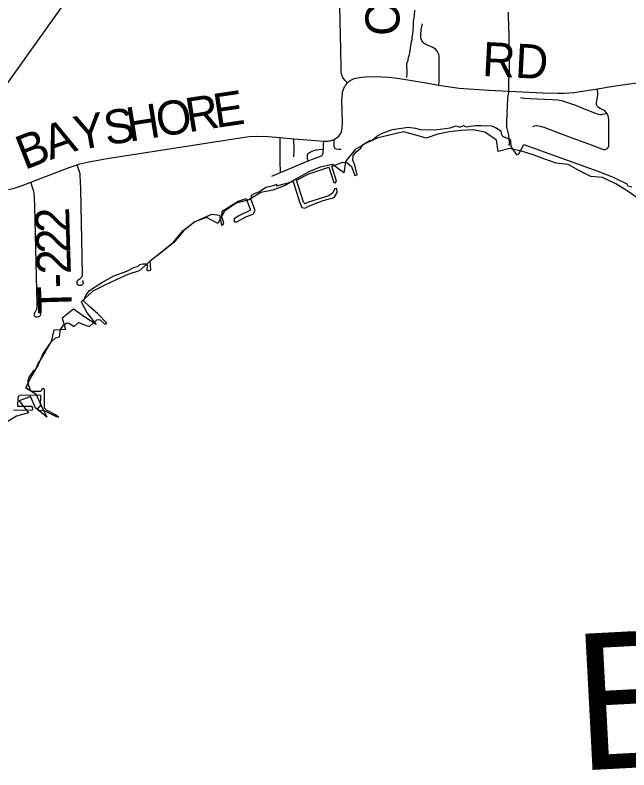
# Model space of a CAD drawing. Extents: x -12 to 34, y 0 to 22.
# Drawn here: x 3.233 to 4.257, y 14.915 to 16.174 of the extents above; entities that cross this region are included whole.
import ezdxf

# ---------------------------------------------------------------- set-up
doc = ezdxf.new("R2010")
doc.units = 0
for name, color, linetype in [('GM_X_Adjacent_County_Text', 7, 'Continuous'), ('GM_X_Airport_Location_Class_2', 7, 'Continuous'), ('GM_X_Airport_Location_Class_3', 7, 'Continuous'), ('GM_X_Corporation', 7, 'Continuous'), ('GM_X_County_Road', 7, 'Continuous'), ('GM_X_County_Road_Text', 7, 'Continuous'), ('GM_X_Major_River', 7, 'Continuous'), ('GM_X_Minor_Lake', 7, 'Continuous'), ('GM_X_Minor_River', 7, 'Continuous')]:
    doc.layers.add(name, color=color, linetype=linetype)

msp = doc.modelspace()

# ---------------------------------------------------------------- linework, layer by layer
at = {"layer": 'GM_X_Airport_Location_Class_2'}
msp.add_lwpolyline([(3.2311, 15.5151), (3.2477, 15.5156), (3.2619, 15.5149), (3.2635, 15.5181), (3.2612, 15.5212), (3.2381, 15.5213), (3.2388, 15.5359), (3.2406, 15.5398), (3.2736, 15.5404), (3.2761, 15.5398), (3.2756, 15.521), (3.2726, 15.5194), (3.271, 15.5171), (3.2726, 15.5145), (3.2801, 15.515), (3.2853, 15.513), (3.301, 15.5051), (3.3057, 15.5035), (3.3007, 15.5074), (3.2859, 15.5151), (3.2826, 15.5184), (3.2828, 15.5499), (3.2801, 15.5512), (3.2783, 15.5494), (3.2764, 15.546), (3.2603, 15.5461), (3.258, 15.551), (3.2557, 15.557), (3.2552, 15.5644), (3.2571, 15.5701), (3.2655, 15.5814), (3.2679, 15.5828), (3.2709, 15.5904), (3.279, 15.6037), (3.2936, 15.6287), (3.3011, 15.6353), (3.3077, 15.6372), (3.3094, 15.6493), (3.3144, 15.6565), (3.3203, 15.6605), (3.3231, 15.66), (3.3322, 15.6543), (3.3394, 15.6612), (3.3535, 15.6553), (3.3576, 15.6543), (3.37, 15.6654), (3.3732, 15.6664), (3.3754, 15.6653), (3.3827, 15.6591), (3.3848, 15.659), (3.3864, 15.6602), (3.3717, 15.6756), (3.3583, 15.6875), (3.3475, 15.6972), (3.3521, 15.7075), (3.3575, 15.7145), (3.378, 15.728), (3.3982, 15.7391), (3.4197, 15.7469), (3.4315, 15.7529), (3.439, 15.7552), (3.4414, 15.758), (3.4464, 15.7592), (3.4519, 15.7592), (3.4538, 15.7568), (3.453, 15.7485), (3.4559, 15.7471), (3.4601, 15.749), (3.4587, 15.7638), (3.4784, 15.7797), (3.4974, 15.7945), (3.5137, 15.8143), (3.5327, 15.8287), (3.5617, 15.8416), (3.5745, 15.8403), (3.5776, 15.8234), (3.5799, 15.8237), (3.5817, 15.8268), (3.5786, 15.8379), (3.5791, 15.8466), (3.6056, 15.8632), (3.6171, 15.8675), (3.619, 15.8678), (3.6262, 15.8483), (3.607, 15.8387), (3.5991, 15.8337), (3.5989, 15.8287), (3.6032, 15.8289), (3.6193, 15.8378), (3.6308, 15.8419), (3.6339, 15.8476), (3.6274, 15.8658), (3.6279, 15.8735), (3.6339, 15.8766), (3.6415, 15.8795), (3.6454, 15.8831), (3.6521, 15.8867), (3.6638, 15.8898), (3.6696, 15.8915), (3.6698, 15.8891), (3.6971, 15.896), (3.7079, 15.8622), (3.712, 15.8527), (3.7166, 15.8515), (3.7228, 15.8553), (3.7472, 15.8644), (3.7655, 15.8697), (3.7707, 15.8778), (3.77, 15.8841), (3.7669, 15.8848), (3.7635, 15.8771), (3.7568, 15.8725), (3.7211, 15.8613), (3.7173, 15.8591), (3.7146, 15.8615), (3.7027, 15.8982), (3.7233, 15.9092), (3.7568, 15.9202), (3.765, 15.8944), (3.7681, 15.8939), (3.7695, 15.897), (3.7621, 15.9219), (3.7801, 15.9286), (3.7873, 15.9272), (3.7947, 15.9212), (3.8002, 15.9061), (3.8041, 15.9071), (3.8002, 15.9236), (3.7971, 15.9315), (3.7976, 15.9394), (3.8024, 15.9459), (3.8098, 15.9514), (3.8139, 15.9581), (3.8256, 15.9653), (3.8288, 15.9648), (3.8369, 15.972), (3.8446, 15.9761), (3.863, 15.983), (3.8891, 15.9866), (3.9014, 15.985), (3.9095, 15.9828), (3.9342, 15.9823), (3.9591, 15.9859), (3.9692, 15.989), (3.9752, 15.9869), (3.9814, 15.9893), (3.986, 15.9874), (3.9934, 15.9883), (4.002, 15.9893), (4.0107, 15.9898), (4.0171, 15.989), (4.0195, 15.9893), (4.0282, 15.989), (4.0349, 15.9864), (4.0435, 15.9806), (4.0445, 15.9763), (4.0466, 15.972), (4.0488, 15.9708), (4.0586, 15.967), (4.06, 15.9641), (4.0603, 15.9548), (4.0701, 15.9404), (4.0737, 15.9421), (4.0821, 15.9581), (4.2058, 15.9133), (4.2312, 15.9037), (4.2539, 15.8924), (4.2554, 15.8888), (4.2621, 15.8874)], dxfattribs=at)
msp.add_lwpolyline([(3.2311, 15.5151), (3.2477, 15.5156), (3.2619, 15.5149), (3.2635, 15.5181), (3.2612, 15.5212), (3.2381, 15.5213), (3.2388, 15.5359), (3.2406, 15.5398), (3.2736, 15.5404), (3.2761, 15.5398), (3.2756, 15.521), (3.2726, 15.5194), (3.271, 15.5171), (3.2726, 15.5145), (3.2801, 15.515), (3.2853, 15.513), (3.301, 15.5051), (3.3057, 15.5035), (3.3007, 15.5074), (3.2859, 15.5151), (3.2826, 15.5184), (3.2828, 15.5499), (3.2801, 15.5512), (3.2783, 15.5494), (3.2764, 15.546), (3.2603, 15.5461), (3.258, 15.551), (3.2557, 15.557), (3.2552, 15.5644), (3.2571, 15.5701), (3.2655, 15.5814), (3.2679, 15.5828), (3.2709, 15.5904), (3.279, 15.6037), (3.2936, 15.6287), (3.3011, 15.6353), (3.3077, 15.6372), (3.3094, 15.6493), (3.3144, 15.6565), (3.3203, 15.6605), (3.3231, 15.66), (3.3322, 15.6543), (3.3394, 15.6612), (3.3535, 15.6553), (3.3576, 15.6543), (3.37, 15.6654), (3.3732, 15.6664), (3.3754, 15.6653), (3.3827, 15.6591), (3.3848, 15.659), (3.3864, 15.6602), (3.3717, 15.6756), (3.3583, 15.6875), (3.3475, 15.6972), (3.3521, 15.7075), (3.3575, 15.7145), (3.378, 15.728), (3.3982, 15.7391), (3.4197, 15.7469), (3.4315, 15.7529), (3.439, 15.7552), (3.4414, 15.758), (3.4464, 15.7592), (3.4519, 15.7592), (3.4538, 15.7568), (3.453, 15.7485), (3.4559, 15.7471), (3.4601, 15.749), (3.4587, 15.7638), (3.4784, 15.7797), (3.4974, 15.7945), (3.5137, 15.8143), (3.5327, 15.8287), (3.5617, 15.8416), (3.5745, 15.8403), (3.5776, 15.8234), (3.5799, 15.8237), (3.5817, 15.8268), (3.5786, 15.8379), (3.5791, 15.8466), (3.6056, 15.8632), (3.6171, 15.8675), (3.619, 15.8678), (3.6262, 15.8483), (3.607, 15.8387), (3.5991, 15.8337), (3.5989, 15.8287), (3.6032, 15.8289), (3.6193, 15.8378), (3.6308, 15.8419), (3.6339, 15.8476), (3.6274, 15.8658), (3.6279, 15.8735), (3.6339, 15.8766), (3.6415, 15.8795), (3.6454, 15.8831), (3.6521, 15.8867), (3.6638, 15.8898), (3.6696, 15.8915), (3.6698, 15.8891), (3.6971, 15.896), (3.7079, 15.8622), (3.712, 15.8527), (3.7166, 15.8515), (3.7228, 15.8553), (3.7472, 15.8644), (3.7655, 15.8697), (3.7707, 15.8778), (3.77, 15.8841), (3.7669, 15.8848), (3.7635, 15.8771), (3.7568, 15.8725), (3.7211, 15.8613), (3.7173, 15.8591), (3.7146, 15.8615), (3.7027, 15.8982), (3.7233, 15.9092), (3.7568, 15.9202), (3.765, 15.8944), (3.7681, 15.8939), (3.7695, 15.897), (3.7621, 15.9219), (3.7801, 15.9286), (3.7873, 15.9272), (3.7947, 15.9212), (3.8002, 15.9061), (3.8041, 15.9071), (3.8002, 15.9236), (3.7971, 15.9315), (3.7976, 15.9394), (3.8024, 15.9459), (3.8098, 15.9514), (3.8139, 15.9581), (3.8256, 15.9653), (3.8288, 15.9648), (3.8369, 15.972), (3.8446, 15.9761), (3.863, 15.983), (3.8891, 15.9866), (3.9014, 15.985), (3.9095, 15.9828), (3.9342, 15.9823), (3.9591, 15.9859), (3.9692, 15.989), (3.9752, 15.9869), (3.9814, 15.9893), (3.986, 15.9874), (3.9934, 15.9883), (4.002, 15.9893), (4.0107, 15.9898), (4.0171, 15.989), (4.0195, 15.9893), (4.0282, 15.989), (4.0349, 15.9864), (4.0435, 15.9806), (4.0445, 15.9763), (4.0466, 15.972), (4.0488, 15.9708), (4.0586, 15.967), (4.06, 15.9641), (4.0603, 15.9548), (4.0701, 15.9404), (4.0737, 15.9421), (4.0821, 15.9581), (4.2058, 15.9133), (4.2312, 15.9037), (4.2539, 15.8924), (4.2554, 15.8888), (4.2621, 15.8874)], dxfattribs=at)
at = {"layer": 'GM_X_Airport_Location_Class_3'}
msp.add_line((3.6759, 15.9693), (3.6984, 15.9675), dxfattribs=at)
for points in [[(3.788, 16.0606), (3.7843, 16.0645), (3.7816, 16.0677), (3.7803, 16.0697), (3.7794, 16.0715), (3.7785, 16.0737), (3.7779, 16.076), (3.7777, 16.0782), (3.7772, 16.0844), (3.7766, 16.1155), (3.7735, 16.2618), (3.7716, 16.349), (3.7682, 16.4923), (3.7675, 16.5162)], [(3.788, 16.0606), (3.7902, 16.0628), (3.7924, 16.0644), (3.7946, 16.0657), (3.7968, 16.0668), (3.7992, 16.0677), (3.8021, 16.0686), (3.8051, 16.0693), (3.8081, 16.0698), (3.8121, 16.0702), (3.8178, 16.0706), (3.8297, 16.071), (3.8452, 16.0708), (3.8576, 16.0702), (3.8668, 16.0693), (3.8822, 16.067), (3.9189, 16.0606), (3.9406, 16.057)], [(3.7655, 15.9663), (3.7665, 15.9668), (3.7691, 15.9682), (3.7712, 15.9699), (3.7734, 15.9719), (3.7753, 15.9742), (3.7769, 15.9767), (3.778, 15.9794), (3.7793, 15.9853), (3.7796, 15.9945), (3.7788, 16.0319), (3.7789, 16.0371), (3.7794, 16.0421), (3.7799, 16.0451), (3.7807, 16.0484), (3.782, 16.0516), (3.7833, 16.0542), (3.7853, 16.0572), (3.788, 16.0606)], [(3.9406, 16.057), (3.9587, 16.0541), (3.9742, 16.052), (3.9897, 16.0507), (4.0239, 16.0487), (4.1139, 16.044), (4.1388, 16.0434), (4.1497, 16.0434), (4.1585, 16.0439), (4.1667, 16.0448), (4.1761, 16.046), (4.1914, 16.0484), (4.2051, 16.0507)], [(4.2051, 16.0507), (4.2313, 16.0551), (4.2977, 16.0646)], [(3.3372, 15.9241), (3.3415, 15.9255), (3.3567, 15.9291), (3.3873, 15.9345), (3.6087, 15.9692), (3.6242, 15.971), (3.6367, 15.9718), (3.6554, 15.971), (3.6759, 15.9693)], [(3.6984, 15.9675), (3.7205, 15.9657), (3.7484, 15.9636)], [(3.7484, 15.9636), (3.7545, 15.9637), (3.7568, 15.964), (3.7584, 15.9642), (3.7605, 15.9646), (3.7616, 15.965), (3.7628, 15.9653), (3.7655, 15.9663)], [(3.26, 15.8951), (3.3237, 15.9197), (3.3372, 15.9241)], [(3.2226, 15.883), (3.2305, 15.8848), (3.2453, 15.8895), (3.26, 15.8951)]]:
    msp.add_lwpolyline(points, dxfattribs=at)
at = {"layer": 'GM_X_Corporation'}
msp.add_lwpolyline([(2.8614, 14.9446), (2.8237, 15.0402), (2.7924, 15.0967), (2.7435, 15.1932), (2.7326, 15.2135), (2.7266, 15.2424), (2.7245, 15.2828), (2.7326, 15.3249), (2.7503, 15.3643), (2.8291, 15.4899), (3.0486, 15.8188), (3.3759, 16.2779), (3.6102, 16.618), (3.6764, 16.6954), (3.7218, 16.7297), (3.762, 16.7538), (3.8349, 16.7817), (3.8869, 16.8002), (4.008, 16.8225), (4.8175, 16.8457)], dxfattribs=at)
at = {"layer": 'GM_X_Major_River'}
msp.add_line((3.6619, 15.9053), (3.676, 15.911), dxfattribs=at)
for points in [[(3.9406, 16.057), (3.9407, 16.0643), (3.9411, 16.0988), (3.9408, 16.1051), (3.9401, 16.1081), (3.9389, 16.111), (3.9374, 16.1137), (3.9353, 16.1161), (3.9329, 16.1181), (3.9303, 16.1198), (3.9187, 16.1247), (3.9161, 16.1264), (3.9138, 16.1286), (3.9121, 16.1311), (3.9109, 16.134), (3.9103, 16.1371), (3.9102, 16.1403), (3.911, 16.1496), (3.913, 16.1589)], [(4.2207, 16.0097), (4.2197, 16.0111), (4.2176, 16.0134), (4.2151, 16.0152), (4.2093, 16.0178), (4.2067, 16.0194), (4.2046, 16.0216), (4.2035, 16.0244), (4.2033, 16.0275), (4.2037, 16.0306), (4.205, 16.0368), (4.2054, 16.0399), (4.2055, 16.043), (4.2052, 16.0496), (4.2051, 16.0507)], [(4.0767, 16.0365), (4.0798, 16.0357), (4.0828, 16.0353), (4.0921, 16.0346), (4.1294, 16.033), (4.1387, 16.0322), (4.1448, 16.031), (4.1567, 16.0274), (4.1684, 16.0234), (4.1829, 16.0173), (4.2003, 16.0106), (4.2061, 16.0087), (4.2092, 16.0081), (4.2117, 16.008), (4.2136, 16.0082), (4.2196, 16.0094), (4.2207, 16.0097)], [(4.0971, 15.9879), (4.1001, 15.9888), (4.1032, 15.9893), (4.1063, 15.9892), (4.1093, 15.9886), (4.1153, 15.9868), (4.1417, 15.977), (4.1592, 15.9702), (4.1943, 15.9571), (4.2119, 15.9504), (4.2149, 15.9496), (4.218, 15.9497), (4.2207, 15.9508), (4.2228, 15.953), (4.2239, 15.9558), (4.2242, 15.9589), (4.224, 15.9996), (4.2236, 16.0027), (4.2228, 16.0057), (4.2215, 16.0085), (4.2207, 16.0097)], [(3.676, 15.911), (3.6758, 15.9297), (3.6759, 15.9693)], [(3.6987, 15.9374), (3.6988, 15.9496), (3.6984, 15.9675)], [(3.7477, 15.9499), (3.7478, 15.9552), (3.748, 15.9591), (3.7484, 15.9636)], [(3.7777, 15.9498), (3.7759, 15.9498), (3.7737, 15.9498), (3.7699, 15.9502), (3.7686, 15.9506), (3.7677, 15.9511), (3.767, 15.9516), (3.7666, 15.9522), (3.7662, 15.9533), (3.766, 15.9543), (3.7659, 15.9553), (3.7658, 15.9561), (3.7657, 15.958), (3.7656, 15.9611), (3.7655, 15.9663)], [(3.7223, 15.9305), (3.7219, 15.9324), (3.7214, 15.9347), (3.7211, 15.9366), (3.721, 15.9378), (3.721, 15.9388), (3.7211, 15.9399), (3.7212, 15.9409), (3.7217, 15.9421), (3.7223, 15.9428), (3.7227, 15.9433), (3.7244, 15.9445), (3.7256, 15.9452), (3.7266, 15.9457), (3.7289, 15.9467), (3.7316, 15.9478), (3.7356, 15.949), (3.7375, 15.9492), (3.7409, 15.9497), (3.7477, 15.9499)], [(3.7223, 15.9305), (3.7342, 15.9351), (3.742, 15.9378), (3.7435, 15.9384), (3.7443, 15.9389), (3.7454, 15.9398), (3.7461, 15.9406), (3.7465, 15.9412), (3.7468, 15.9419), (3.7471, 15.9428), (3.7474, 15.9436), (3.7475, 15.9447), (3.7476, 15.9457), (3.7477, 15.9499)], [(3.3457, 15.7313), (3.3461, 15.7306), (3.3466, 15.7292), (3.3469, 15.7283), (3.3469, 15.7272), (3.3468, 15.7262), (3.3465, 15.7255), (3.3458, 15.7244), (3.3449, 15.7235), (3.344, 15.7231), (3.343, 15.7229), (3.3419, 15.7227), (3.3406, 15.7228), (3.3396, 15.7231), (3.3386, 15.7236), (3.3381, 15.7241), (3.3373, 15.7248), (3.337, 15.7257), (3.3368, 15.7266), (3.3367, 15.7277), (3.3369, 15.7286), (3.3371, 15.7295), (3.3374, 15.7303), (3.3379, 15.7309), (3.3384, 15.7315), (3.3389, 15.732), (3.3397, 15.7327), (3.3415, 15.7342), (3.3436, 15.7359), (3.3447, 15.737), (3.3454, 15.7379), (3.3456, 15.7385), (3.3459, 15.7399), (3.3461, 15.7418), (3.343, 15.8843), (3.3422, 15.906), (3.3419, 15.9089), (3.3417, 15.9104), (3.3412, 15.9122), (3.3406, 15.9138), (3.3372, 15.9241)], [(3.676, 15.911), (3.6937, 15.9183), (3.7196, 15.9295), (3.7223, 15.9305)], [(3.274, 15.6789), (3.2749, 15.6778), (3.2754, 15.6767), (3.2757, 15.6753), (3.2757, 15.6743), (3.2755, 15.6735), (3.2752, 15.6726), (3.2747, 15.6719), (3.2743, 15.6713), (3.2731, 15.6704), (3.2725, 15.6703), (3.2704, 15.6701), (3.2693, 15.6701), (3.2685, 15.6704), (3.2678, 15.6707), (3.2672, 15.6711), (3.2665, 15.6719), (3.266, 15.6728), (3.2657, 15.6736), (3.2656, 15.6744), (3.2656, 15.6756), (3.2657, 15.6762), (3.2659, 15.677), (3.2664, 15.678), (3.2668, 15.6786), (3.2675, 15.6796), (3.2688, 15.6815), (3.2696, 15.6829), (3.27, 15.6846), (3.2702, 15.6861), (3.2704, 15.6892), (3.2704, 15.6913), (3.2662, 15.8548), (3.2656, 15.8698), (3.2651, 15.8766), (3.2646, 15.8801), (3.2639, 15.8827), (3.26, 15.8951)]]:
    msp.add_lwpolyline(points, dxfattribs=at)
at = {"layer": 'GM_X_Minor_Lake'}
for points in [[(3.886, 16.0696), (3.8871, 16.0707), (3.8871, 16.0718), (3.8875, 16.0741), (3.8876, 16.0779), (3.8873, 16.0828), (3.887, 16.0855), (3.887, 16.0897), (3.8867, 16.0927), (3.8875, 16.0946), (3.889, 16.098), (3.8894, 16.1007), (3.891, 16.106), (3.8919, 16.1105), (3.8927, 16.1147), (3.8931, 16.1185), (3.8939, 16.1219), (3.8944, 16.126), (3.8948, 16.1291), (3.8956, 16.1332), (3.8961, 16.137), (3.8969, 16.142), (3.8973, 16.1473), (3.8978, 16.1514), (3.8982, 16.1533), (3.8983, 16.1628), (3.8987, 16.1655), (3.8992, 16.1689), (3.8996, 16.1723), (3.9, 16.1734), (3.9001, 16.1818)], [(4.0572, 15.9563), (4.058, 15.9581), (4.058, 15.9597), (4.0584, 15.96), (4.058, 15.9616), (4.0577, 15.9673), (4.0571, 15.9733), (4.0542, 15.9848), (4.0538, 15.9863), (4.0539, 15.9874), (4.0537, 15.9992), (4.0545, 16.0064), (4.0549, 16.0079), (4.0546, 16.0114), (4.0547, 16.0205), (4.0557, 16.036), (4.057, 16.0444), (4.0574, 16.0463), (4.0574, 16.0474), (4.0572, 16.0577), (4.0573, 16.0656), (4.0582, 16.0751), (4.0583, 16.085), (4.0581, 16.0945), (4.0578, 16.1032), (4.0576, 16.1116), (4.0577, 16.1211), (4.0575, 16.1325), (4.0577, 16.1431), (4.0574, 16.1511), (4.0571, 16.1587), (4.0565, 16.1689), (4.0567, 16.1784)]]:
    msp.add_lwpolyline(points, dxfattribs=at)
at = {"layer": 'GM_X_Minor_River'}
for points in [[(4.2743, 15.8668), (4.2546, 15.8808), (4.2356, 15.8922), (4.2136, 15.9028), (4.1939, 15.9047), (4.1749, 15.9142), (4.1559, 15.9245), (4.1362, 15.9268), (4.1172, 15.9332), (4.0975, 15.9408), (4.0781, 15.9465), (4.0588, 15.9514), (4.0391, 15.9461), (4.0368, 15.9651), (4.017, 15.9784), (3.9977, 15.9822), (3.9776, 15.9814), (3.9578, 15.9788), (3.9389, 15.975), (3.9195, 15.9685), (3.9005, 15.9738), (3.8816, 15.9788), (3.8603, 15.9742), (3.8394, 15.9689), (3.8201, 15.9605), (3.8007, 15.9495), (3.7848, 15.9297), (3.7818, 15.9104), (3.7628, 15.9248), (3.7423, 15.9199), (3.7233, 15.9123), (3.7044, 15.902), (3.6839, 15.8898), (3.6634, 15.8815), (3.6433, 15.8781), (3.6232, 15.8655), (3.6023, 15.8598), (3.5829, 15.8465), (3.5716, 15.8264), (3.5526, 15.8363), (3.5336, 15.8287), (3.5146, 15.8142), (3.4983, 15.7945), (3.4793, 15.7796), (3.4596, 15.7637), (3.4403, 15.7474), (3.4213, 15.7413), (3.4019, 15.7321), (3.3822, 15.7226), (3.3632, 15.7131), (3.3439, 15.6957), (3.3538, 15.6767), (3.3689, 15.6577), (3.35, 15.6702), (3.331, 15.6831), (3.312, 15.6683), (3.3177, 15.6493), (3.2984, 15.6486), (3.2934, 15.6292), (3.2801, 15.6102), (3.2718, 15.5903), (3.26, 15.57), (3.2513, 15.5528)], [(4.2743, 15.8668), (4.2546, 15.8808), (4.2356, 15.8922), (4.2136, 15.9028), (4.1939, 15.9047), (4.1749, 15.9142), (4.1559, 15.9245), (4.1362, 15.9268), (4.1172, 15.9332), (4.0975, 15.9408), (4.0781, 15.9465), (4.0588, 15.9514), (4.0391, 15.9461), (4.0368, 15.9651), (4.017, 15.9784), (3.9977, 15.9822), (3.9776, 15.9814), (3.9578, 15.9788), (3.9389, 15.975), (3.9195, 15.9685), (3.9005, 15.9738), (3.8816, 15.9788), (3.8603, 15.9742), (3.8394, 15.9689), (3.8201, 15.9605), (3.8007, 15.9495), (3.7848, 15.9297), (3.7818, 15.9104), (3.7628, 15.9248), (3.7423, 15.9199), (3.7233, 15.9123), (3.7044, 15.902), (3.6839, 15.8898), (3.6634, 15.8815), (3.6433, 15.8781), (3.6232, 15.8655), (3.6023, 15.8598), (3.5829, 15.8465), (3.5716, 15.8264), (3.5526, 15.8363), (3.5336, 15.8287), (3.5146, 15.8142), (3.4983, 15.7945), (3.4793, 15.7796), (3.4596, 15.7637), (3.4403, 15.7474), (3.4213, 15.7413), (3.4019, 15.7321), (3.3822, 15.7226), (3.3632, 15.7131), (3.3439, 15.6957), (3.3538, 15.6767), (3.3689, 15.6577), (3.35, 15.6702), (3.331, 15.6831), (3.312, 15.6683), (3.3177, 15.6493), (3.2984, 15.6486), (3.2934, 15.6292), (3.2801, 15.6102), (3.2718, 15.5903), (3.26, 15.57), (3.2514, 15.5522)], [(3.2513, 15.5528), (3.2681, 15.5421), (3.2772, 15.5227), (3.2863, 15.5034), (3.2673, 15.5186), (3.2594, 15.5376), (3.2404, 15.5307), (3.2556, 15.5106), (3.2358, 15.5052), (3.2161, 15.4927), (3.2066, 15.4706), (3.199, 15.4516), (3.1922, 15.4322), (3.1835, 15.4117)], [(3.2514, 15.5522), (3.2681, 15.5421), (3.2772, 15.5227), (3.2863, 15.5034), (3.2673, 15.5186), (3.2594, 15.5376), (3.2404, 15.5307), (3.2556, 15.5106), (3.2358, 15.5052), (3.2161, 15.4927), (3.2066, 15.4706), (3.199, 15.4516), (3.1922, 15.4322), (3.1835, 15.4117)]]:
    msp.add_lwpolyline(points, dxfattribs=at)

# ---------------------------------------------------------------- texts
at = {"layer": 'GM_X_Adjacent_County_Text'}
msp.add_text('B A Y', height=0.22741, rotation=3.0064, dxfattribs=at).set_placement((4.1718, 14.9139))
at = {"layer": 'GM_X_County_Road'}
for s, height, rotation, p in [('C-137', 0.05682, 91.1032, (3.8753, 16.1394)), ('RD', 0.05682, 357.0387, (4.0119, 16.0723)), ('E', 0.0568, 8.4625, (3.5686, 15.9854)), ('O', 0.0568, 9.0024, (3.4732, 15.9703)), ('R', 0.0568, 8.9862, (3.5226, 15.9781)), ('H', 0.0568, 9.0042, (3.4239, 15.9624)), ('Y', 0.0568, 10.1475, (3.3371, 15.9477)), ('S', 0.0568, 9.0194, (3.386, 15.9564)), ('A', 0.0568, 19.2546, (3.2922, 15.9318)), ('B', 0.0568, 21.393, (3.2493, 15.915))]:
    msp.add_text(s, height=height, rotation=rotation, dxfattribs=at).set_placement(p)
at = {"layer": 'GM_X_County_Road_Text'}
for s, rotation, p in [('2', 91.7358, (3.3247, 15.8117)), ('2', 91.6919, (3.3257, 15.7769)), ('2', 91.6709, (3.3267, 15.7422)), ('-', 91.6643, (3.3274, 15.719)), ('T', 91.6626, (3.3286, 15.6766))]:
    msp.add_text(s, height=0.0568, rotation=rotation, dxfattribs=at).set_placement(p)

doc.saveas('drawing.dxf')
